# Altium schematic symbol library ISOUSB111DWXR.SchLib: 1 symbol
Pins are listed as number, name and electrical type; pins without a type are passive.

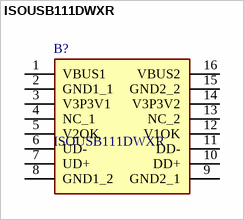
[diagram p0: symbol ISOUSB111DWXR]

## ISOUSB111DWXR
designator B?
USB Interface IC Low emissions, full and low speed isolated USB repeater 16-SSOP -40 to 125; Manufacturer_Name: Texas Instruments; Geometry.Height: 2.6mm
footprint SOP65P1030X260-16N
pins: 1 VBUS1, 2 GND1_1, 3 V3P3V1, 4 NC_1, 5 V2OK, 6 UD-, 7 UD+, 8 GND1_2, 9 GND2_1, 10 DD+, 11 DD-, 12 V1OK, 13 NC_2, 14 V3P3V2, 15 GND2_2, 16 VBUS2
